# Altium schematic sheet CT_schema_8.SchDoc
size 274 x 160 mm
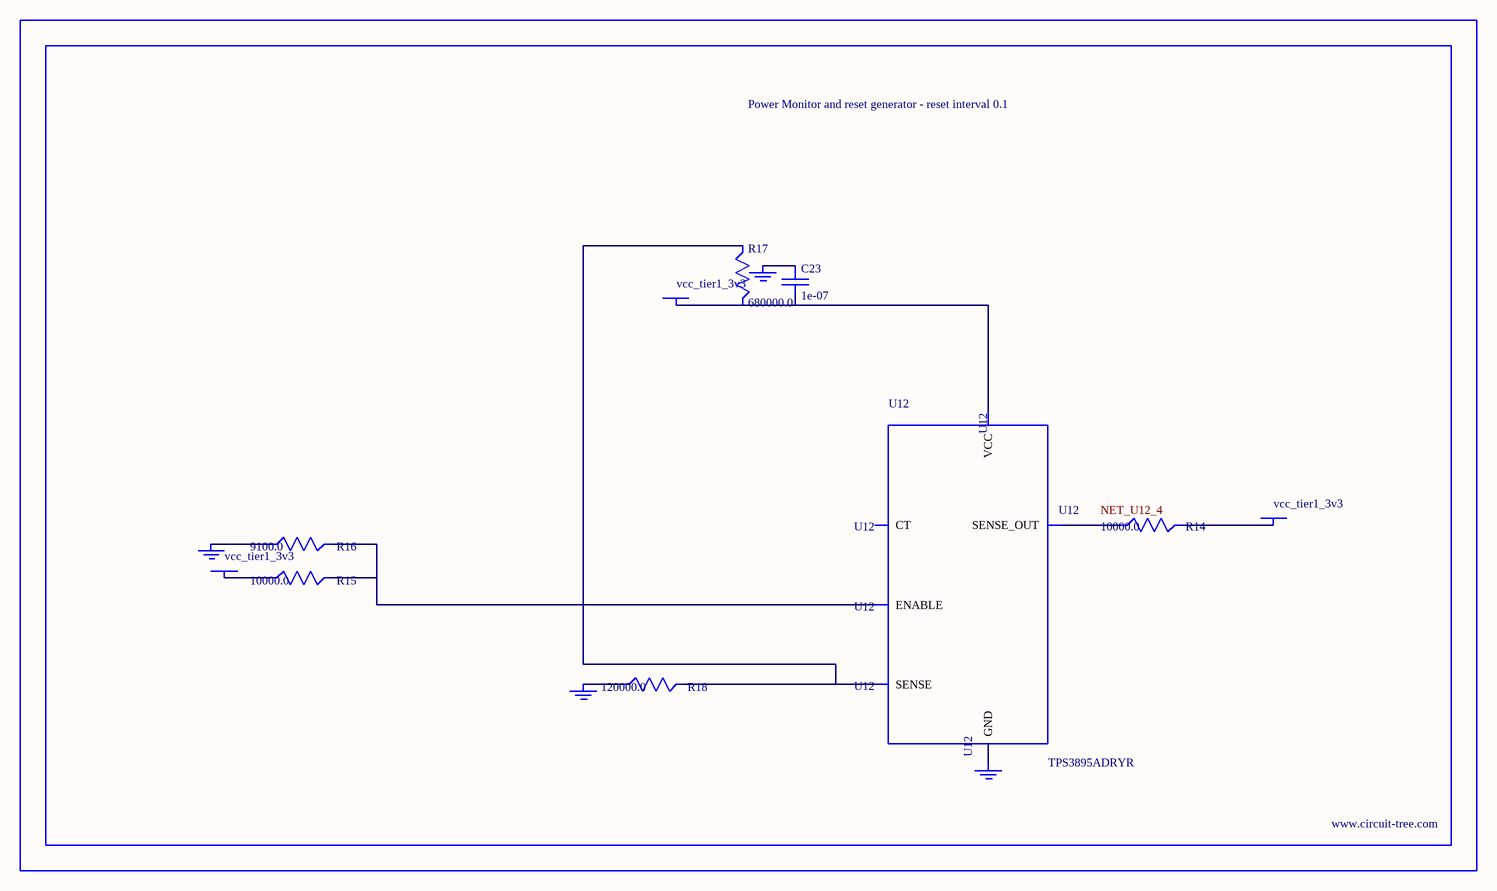
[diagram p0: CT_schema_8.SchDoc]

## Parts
BORDER7  (no value)
C23  1e-07  [C0402]
GND_INSTANCE_7_0  (no value)
GND_INSTANCE_7_1  (no value)
GND_INSTANCE_7_2  (no value)
GND_INSTANCE_7_3  (no value)
POWER_INSTANCE_7_0  vcc_tier1_3v3
POWER_INSTANCE_7_1  vcc_tier1_3v3
POWER_INSTANCE_7_2  vcc_tier1_3v3
R14  10000.0  [R0603]
R15  10000.0  [R0603]
R16  9100.0  [R0603]
R17  680000.0  [R0603]
R18  120000.0  [R0603]
U12  TPS3895ADRYR  [SON-6]

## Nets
NetC23_1: C23.1 GND_INSTANCE_7_2.0(GND)
NetC23_2: C23.2 POWER_INSTANCE_7_2.0(PWR) R17.2 U12.6(VCC)
NetGND_INSTANCE_7_0_0: GND_INSTANCE_7_0.0(GND) R16.1
NetGND_INSTANCE_7_1_0: GND_INSTANCE_7_1.0(GND) R18.1
NetGND_INSTANCE_7_3_0: GND_INSTANCE_7_3.0(GND) U12.2(GND)
NetPOWER_INSTANCE_7_0_0: POWER_INSTANCE_7_0.0(PWR) R15.1
NetPOWER_INSTANCE_7_1_0: POWER_INSTANCE_7_1.0(PWR) R14.2
NetR14_1: R14.1 U12.4(SENSE_OUT)
NetR15_2: R15.2 R16.2 U12.1(ENABLE)
NetR17_1: R17.1 R18.2 U12.3(SENSE)

Not connected (* = marked no-connect by the designer): U12 5(CT)

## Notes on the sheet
- Labels drawn without touching a wire or pin: NET_U12_4

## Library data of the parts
BORDER7 = BORDER_PAGE7
C23 = C0402C104K3RACTU
GND_INSTANCE_7_0-GND_INSTANCE_7_3 = GND
POWER_INSTANCE_7_0-POWER_INSTANCE_7_2 = PWR
R14 R15 = RC0603JR-0710KL
R16 = RC0603JR-079K1L
R17 = RC0603JR-07680KL
R18 = RC0603JR-07120KL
